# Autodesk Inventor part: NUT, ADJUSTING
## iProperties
Title: NUT, ADJUSTING
Author: E. MOSS
Revision Number: A
Shininess: 41.0
PropertySet Name: _Private Model Information
Created: 2000-11
Part Number: N101
Project: ACME
Description: NUT, ADJUSTING
Document SubType Name: Modeling
Designer: Administrator
Control State: 0
Master: False
Checked Out: False
PropertySet Name: Design Tracking Control
Density: 0.0
Volumn: 0.0
Area: 0.0
PropertySet Name: Model Information
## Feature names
1. Revolution1
2. Extrusion1
3. Revolution2
4. Extrusion2
5. Fillet1
